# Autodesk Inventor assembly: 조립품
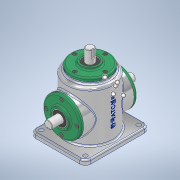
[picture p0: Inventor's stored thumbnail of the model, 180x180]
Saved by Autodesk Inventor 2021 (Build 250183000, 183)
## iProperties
Created: 2021-02
Part Number: 조립품
Document SubType Name: Assembly
Designer: 201-20
Author: 201-20
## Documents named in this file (16)
- C:\Users\201-20\Downloads\710214V1007\조립품.iam
- C:\Users\201-20\Downloads\710214V1007\본채.ipt
- C:\Users\201-20\Downloads\710214V1007\커버.ipt
- C:\Users\201-20\Downloads\710214V1007\메인 축.ipt
- 메인 축.ipt
- C:\Users\201-20\Downloads\710214V1007\베어링 6203.ipt
- C:\Users\201-20\Downloads\710214V1007\메인 베벨기어.ipt
- C:\Users\201-20\Downloads\710214V1007\오일 실.ipt
- 오일 실.ipt
- C:\Users\201-20\Downloads\710214V1007\서브 축.ipt
- 서브 축.ipt
- C:\Users\201-20\Downloads\710214V1007\서브 베벨기어.ipt
- C:\Users\201-20\Downloads\710214V1007\키 5x5.ipt
- C:\Users\201-20\Downloads\710214V1007\키 4x4.ipt
- C:\Users\201-20\Downloads\710214V1007\볼트 M4.ipt
- 볼트 M4.ipt
